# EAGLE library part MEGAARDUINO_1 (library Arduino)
The Arduino Mega is a microcontroller board based on the ATmega1280. - 54 digital input/output pins (of which 14 can be used as PWM outputs) - 16 analog inputs - 4 UARTs (hardware serial ports) - 16 MHz crystal oscillator - USB connection - power jack - ICSP header - reset button It contains everything needed to support the microcontroller; simply connect it to a computer with a USB cable or power it with a AC-to-DC adapter or battery to get started. The Mega is compatible with most shields designed for the Arduino Duemilanove or Diecimila. http://arduino.cc/en/Main/ArduinoBoardMega
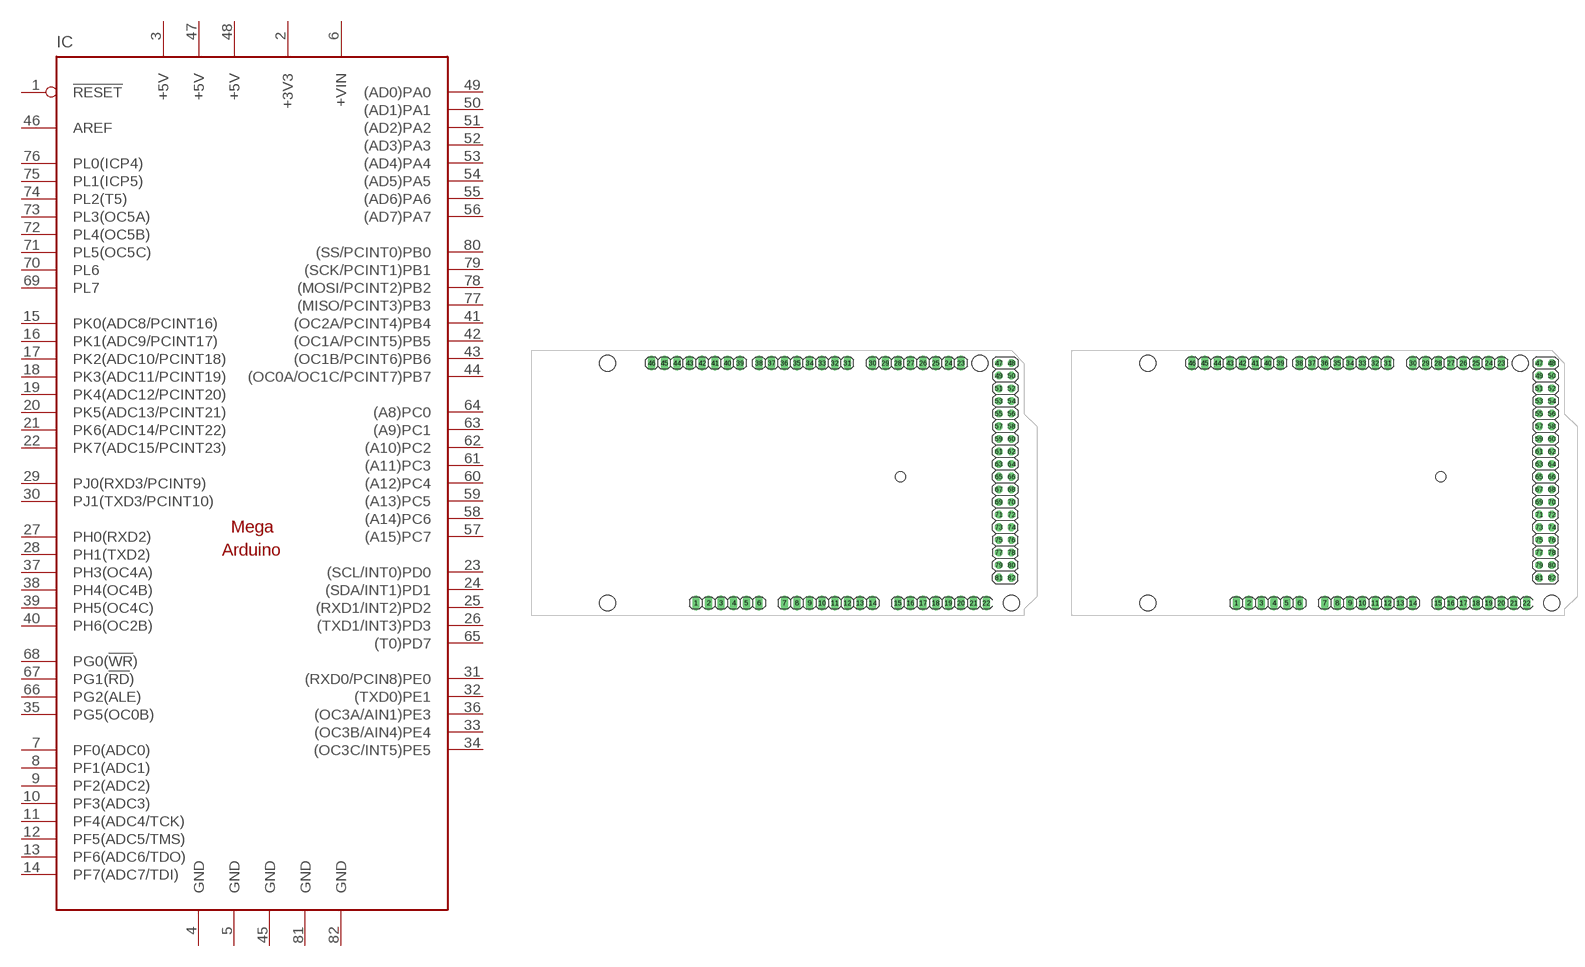
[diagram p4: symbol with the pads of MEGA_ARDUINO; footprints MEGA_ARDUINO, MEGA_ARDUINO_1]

Designator prefix IC

## MEGAARDUINO_1  [MEGA_ARDUINO]
1  !RESET
2  +3V3  pwr
3  +5V  pwr
4  GND  pwr
5  GND  pwr
6  +VIN  pwr
7  PF0(ADC0)
8  PF1(ADC1)
9  PF2(ADC2)
10  PF3(ADC3)
11  PF4(ADC4/TCK)
12  PF5(ADC5/TMS)
13  PF6(ADC6/TDO)
14  PF7(ADC7/TDI)
15  PK0(ADC8/PCINT16)
16  PK1(ADC9/PCINT17)
17  PK2(ADC10/PCINT18)
18  PK3(ADC11/PCINT19)
19  PK4(ADC12/PCINT20)
20  PK5(ADC13/PCINT21)
21  PK6(ADC14/PCINT22)
22  PK7(ADC15/PCINT23)
23  (SCL/INT0)PD0
24  (SDA/INT1)PD1
25  (RXD1/INT2)PD2
26  (TXD1/INT3)PD3
27  PH0(RXD2)
28  PH1(TXD2)
29  PJ0(RXD3/PCINT9)
30  PJ1(TXD3/PCINT10)
31  (RXD0/PCIN8)PE0
32  (TXD0)PE1
33  (OC3B/AIN4)PE4
34  (OC3C/INT5)PE5
35  PG5(OC0B)
36  (OC3A/AIN1)PE3
37  PH3(OC4A)
38  PH4(OC4B)
39  PH5(OC4C)
40  PH6(OC2B)
41  (OC2A/PCINT4)PB4
42  (OC1A/PCINT5)PB5
43  (OC1B/PCINT6)PB6
44  (OC0A/OC1C/PCINT7)PB7
45  GND  pwr
46  AREF
47  +5V  pwr
48  +5V  pwr
49  (AD0)PA0
50  (AD1)PA1
51  (AD2)PA2
52  (AD3)PA3
53  (AD4)PA4
54  (AD5)PA5
55  (AD6)PA6
56  (AD7)PA7
57  (A15)PC7
58  (A14)PC6
59  (A13)PC5
60  (A12)PC4
61  (A11)PC3
62  (A10)PC2
63  (A9)PC1
64  (A8)PC0
65  (T0)PD7
66  PG2(ALE)
67  PG1(!RD!)
68  PG0(!WR!)
69  PL7
70  PL6
71  PL5(OC5C)
72  PL4(OC5B)
73  PL3(OC5A)
74  PL2(T5)
75  PL1(ICP5)
76  PL0(ICP4)
77  (MISO/PCINT3)PB3
78  (MOSI/PCINT2)PB2
79  (SCK/PCINT1)PB1
80  (SS/PCINT0)PB0
81  GND  pwr
82  GND  pwr

## MEGAARDUINO_11  [MEGA_ARDUINO_1]
Pads as for MEGA_ARDUINO

## MEGAARDUINO_12  [MEGA_ARDUINO_2]
Pads as for MEGA_ARDUINO

## Footprint MEGA_ARDUINO (pad centres in mm)
drill 1.016 long: 1 33.02,2.54; 2 35.56,2.54; 3 38.1,2.54; 4 40.64,2.54; 5 43.18,2.54; 6 45.72,2.54; 7 50.8,2.54; 8 53.34,2.54; 9 55.88,2.54; 10 58.42,2.54; 11 60.96,2.54; 12 63.5,2.54; 13 66.04,2.54; 14 68.58,2.54; 15 73.66,2.54; 16 76.2,2.54; 17 78.74,2.54; 18 81.28,2.54; 19 83.82,2.54; 20 86.36,2.54; 21 88.9,2.54; 22 91.44,2.54; 23 86.36,50.8; 24 83.82,50.8; 25 81.28,50.8; 26 78.74,50.8; 27 76.2,50.8; 28 73.66,50.8; 29 71.12,50.8; 30 68.58,50.8; 31 63.5,50.8; 32 60.96,50.8; 33 58.42,50.8; 34 55.88,50.8; 35 53.34,50.8; 36 50.8,50.8; 37 48.26,50.8; 38 45.72,50.8; 39 41.91,50.8; 40 39.37,50.8; 41 36.83,50.8; 42 34.29,50.8; 43 31.75,50.8; 44 29.21,50.8; 45 26.67,50.8; 46 24.13,50.8
drill 1.016 octagon: 47 93.98,50.8; 48 96.52,50.8; 49 93.98,48.26; 50 96.52,48.26; 51 93.98,45.72; 52 96.52,45.72; 53 93.98,43.18; 54 96.52,43.18; 55 93.98,40.64; 56 96.52,40.64; 57 93.98,38.1; 58 96.52,38.1; 59 93.98,35.56; 60 96.52,35.56; 61 93.98,33.02; 62 96.52,33.02; 63 93.98,30.48; 64 96.52,30.48; 65 93.98,27.94; 66 96.52,27.94; 67 93.98,25.4; 68 96.52,25.4; 69 93.98,22.86; 70 96.52,22.86; 71 93.98,20.32; 72 96.52,20.32; 73 93.98,17.78; 74 96.52,17.78; 75 93.98,15.24; 76 96.52,15.24; 77 93.98,12.7; 78 96.52,12.7; 79 93.98,10.16; 80 96.52,10.16; 81 93.98,7.62; 82 96.52,7.62
hole 3.2 at 15.24,50.8
hole 3.2 at 15.24,2.54
hole 3.2 at 90.17,50.8
hole 3.2 at 96.52,2.54
hole 2 at 74.168,27.94

## Footprint MEGA_ARDUINO_1 (pad centres in mm)
drill 1.016 long: 1 33.02,2.54; 2 35.56,2.54; 3 38.1,2.54; 4 40.64,2.54; 5 43.18,2.54; 6 45.72,2.54; 7 50.8,2.54; 8 53.34,2.54; 9 55.88,2.54; 10 58.42,2.54; 11 60.96,2.54; 12 63.5,2.54; 13 66.04,2.54; 14 68.58,2.54; 15 73.66,2.54; 16 76.2,2.54; 17 78.74,2.54; 18 81.28,2.54; 19 83.82,2.54; 20 86.36,2.54; 21 88.9,2.54; 22 91.44,2.54; 23 86.36,50.8; 24 83.82,50.8; 25 81.28,50.8; 26 78.74,50.8; 27 76.2,50.8; 28 73.66,50.8; 29 71.12,50.8; 30 68.58,50.8; 31 63.5,50.8; 32 60.96,50.8; 33 58.42,50.8; 34 55.88,50.8; 35 53.34,50.8; 36 50.8,50.8; 37 48.26,50.8; 38 45.72,50.8; 39 41.91,50.8; 40 39.37,50.8; 41 36.83,50.8; 42 34.29,50.8; 43 31.75,50.8; 44 29.21,50.8; 45 26.67,50.8; 46 24.13,50.8
drill 1.016 octagon: 47 93.98,50.8; 48 96.52,50.8; 49 93.98,48.26; 50 96.52,48.26; 51 93.98,45.72; 52 96.52,45.72; 53 93.98,43.18; 54 96.52,43.18; 55 93.98,40.64; 56 96.52,40.64; 57 93.98,38.1; 58 96.52,38.1; 59 93.98,35.56; 60 96.52,35.56; 61 93.98,33.02; 62 96.52,33.02; 63 93.98,30.48; 64 96.52,30.48; 65 93.98,27.94; 66 96.52,27.94; 67 93.98,25.4; 68 96.52,25.4; 69 93.98,22.86; 70 96.52,22.86; 71 93.98,20.32; 72 96.52,20.32; 73 93.98,17.78; 74 96.52,17.78; 75 93.98,15.24; 76 96.52,15.24; 77 93.98,12.7; 78 96.52,12.7; 79 93.98,10.16; 80 96.52,10.16; 81 93.98,7.62; 82 96.52,7.62
hole 3.2 at 15.24,50.8
hole 3.2 at 15.24,2.54
hole 3.2 at 90.17,50.8
hole 3.2 at 96.52,2.54
hole 2 at 74.168,27.94

## Footprint MEGA_ARDUINO_2 (pad centres in mm)
drill 1.016 long: 1 33.02,2.54; 2 35.56,2.54; 3 38.1,2.54; 4 40.64,2.54; 5 43.18,2.54; 6 45.72,2.54; 7 50.8,2.54; 8 53.34,2.54; 9 55.88,2.54; 10 58.42,2.54; 11 60.96,2.54; 12 63.5,2.54; 13 66.04,2.54; 14 68.58,2.54; 15 73.66,2.54; 16 76.2,2.54; 17 78.74,2.54; 18 81.28,2.54; 19 83.82,2.54; 20 86.36,2.54; 21 88.9,2.54; 22 91.44,2.54; 23 86.36,50.8; 24 83.82,50.8; 25 81.28,50.8; 26 78.74,50.8; 27 76.2,50.8; 28 73.66,50.8; 29 71.12,50.8; 30 68.58,50.8; 31 63.5,50.8; 32 60.96,50.8; 33 58.42,50.8; 34 55.88,50.8; 35 53.34,50.8; 36 50.8,50.8; 37 48.26,50.8; 38 45.72,50.8; 39 41.91,50.8; 40 39.37,50.8; 41 36.83,50.8; 42 34.29,50.8; 43 31.75,50.8; 44 29.21,50.8; 45 26.67,50.8; 46 24.13,50.8
drill 1.016 octagon: 47 93.98,50.8; 48 96.52,50.8; 49 93.98,48.26; 50 96.52,48.26; 51 93.98,45.72; 52 96.52,45.72; 53 93.98,43.18; 54 96.52,43.18; 55 93.98,40.64; 56 96.52,40.64; 57 93.98,38.1; 58 96.52,38.1; 59 93.98,35.56; 60 96.52,35.56; 61 93.98,33.02; 62 96.52,33.02; 63 93.98,30.48; 64 96.52,30.48; 65 93.98,27.94; 66 96.52,27.94; 67 93.98,25.4; 68 96.52,25.4; 69 93.98,22.86; 70 96.52,22.86; 71 93.98,20.32; 72 96.52,20.32; 73 93.98,17.78; 74 96.52,17.78; 75 93.98,15.24; 76 96.52,15.24; 77 93.98,12.7; 78 96.52,12.7; 79 93.98,10.16; 80 96.52,10.16; 81 93.98,7.62; 82 96.52,7.62
hole 3.2 at 15.24,50.8
hole 3.2 at 15.24,2.54
hole 3.2 at 90.17,50.8
hole 3.2 at 96.52,2.54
